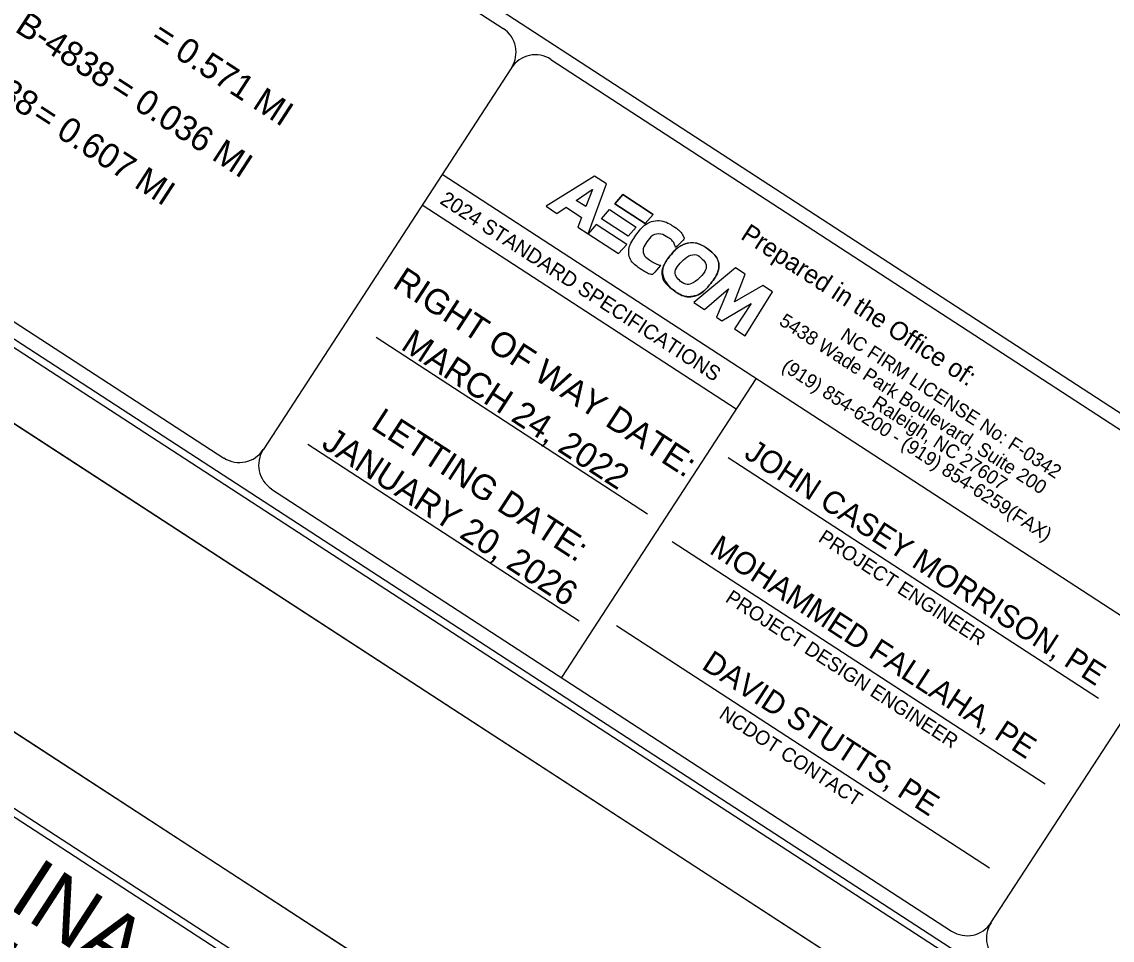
# Model space of a CAD drawing. Extents: x 2291197 to 2302790, y 592892 to 604246.
# Drawn here: x 2296768 to 2298300, y 597905 to 599195 of the extents above; entities that cross this region are included whole.
import ezdxf

# ---------------------------------------------------------------- set-up
doc = ezdxf.new("R2010")
doc.units = 0
for name, color, linetype in [('Default', 7, 'Continuous'), ('Prop DSN Text', 7, 'Continuous'), ('Prop Shade Light', 7, 'Continuous'), ('Sheet Cutting Line CELL', 7, 'Continuous'), ('Sheet Data Field CELL', 7, 'Continuous'), ('Sheet Plot Border Inside CELL', 7, 'Continuous'), ('Sheet Plot Border Outside CELL', 7, 'Continuous'), ('Sheet Symbology CELL', 7, 'Continuous'), ('Sheet Title CELL', 7, 'Continuous')]:
    doc.layers.add(name, color=color, linetype=linetype)

# ---------------------------------------------------------------- blocks, each defined once
blk = doc.blocks.new('block 3')
at = {"layer": 'Default'}
blk.add_open_spline([(0.12275, 0.09393), (0.12554, 0.09373), (0.12726, 0.09146), (0.12695, 0.08843), (0.12663, 0.08531), (0.12411, 0.08298), (0.12127, 0.08318), (0.11848, 0.08338), (0.11676, 0.08565), (0.11707, 0.08868), (0.11739, 0.0918), (0.11991, 0.09413), (0.12275, 0.09393)], degree=3, dxfattribs=at)
blk = doc.blocks.new('PLAN SHEET SYMBOLOGY - New')
at = {"layer": 'Sheet Cutting Line CELL'}
blk.add_line((1439376.56, 921733.15), (1437692.56, 921733.15), dxfattribs=at)
at = {"layer": 'Sheet Plot Border Inside CELL'}
blk.add_lwpolyline([(1437705.56, 920655.6), (1439372.06, 920655.6), (1439372.06, 921710.7), (1437705.56, 921710.7)], close=True, dxfattribs=at)
at = {"layer": 'Sheet Plot Border Outside CELL'}
blk.add_lwpolyline([(1437692.56, 920633.15), (1439376.56, 920633.15), (1439376.56, 921733.15), (1437692.56, 921733.15)], close=True, dxfattribs=at)
at = {"layer": 'Sheet Symbology CELL'}
blk.add_lwpolyline([(1439359.56, 921708.15), (1437859.56, 921708.15), (1437859.56, 920659.17), (1439359.56, 920659.17)], close=True, dxfattribs=at)
for s, height, p in [('STATE OF NORTH CAROLINA, DIVISION OF HIGHWAYS', 21.419, (1438310.12, 921680.19)), ('CONVENTIONAL  PLAN SHEET SYMBOLS', 22.0323, (1438318.25, 921649.31))]:
    blk.add_text(s, height=height, dxfattribs=at).set_placement(p)

msp = doc.modelspace()

# ---------------------------------------------------------------- linework, layer by layer
at = {"layer": 'Prop DSN Text'}
for p, q in [((2297572.8, 598978.2), (2297504.6, 598936)), ((2297563.8, 598897.5), (2297589.3, 598967.5)), ((2297589.3, 598967.5), (2297572.8, 598978.2)), ((2297546.9, 598944.4), (2297569.5, 598959.8)), ((2297569.6, 598959.7), (2297560.4, 598935.7)), ((2297569.5, 598959.8), (2297569.6, 598959.7)), ((2297612.5, 598952.4), (2297601.1, 598939.7)), ((2297655.3, 598924.6), (2297612.5, 598952.4)), ((2297504.6, 598936), (2297519.9, 598926)), ((2297519.9, 598926), (2297532.6, 598934.7)), ((2297532.6, 598934.7), (2297554.5, 598920.4)), ((2297560.4, 598935.7), (2297546.9, 598944.4)), ((2297601.1, 598939.7), (2297643.9, 598911.8)), ((2297554.5, 598920.4), (2297549.3, 598906.9)), ((2297582.5, 598918.6), (2297593.8, 598931.4)), ((2297593.8, 598931.4), (2297631.4, 598906.9)), ((2297643.9, 598911.8), (2297655.3, 598924.6)), ((2297549.3, 598906.9), (2297563.8, 598897.5)), ((2297575.1, 598910.3), (2297563.8, 598897.5)), ((2297617.9, 598882.5), (2297575.1, 598910.3)), ((2297620.1, 598894.1), (2297582.5, 598918.6)), ((2297631.4, 598906.9), (2297620.1, 598894.1)), ((2297563.8, 598897.5), (2297606.6, 598869.7)), ((2297606.6, 598869.7), (2297617.9, 598882.5)), ((2297770.7, 598849.6), (2297712.2, 598801)), ((2297784.4, 598840.6), (2297770.7, 598849.6)), ((2297769.2, 598801.7), (2297784.4, 598840.6)), ((2297727.4, 598791.1), (2297760.8, 598820.1)), ((2297760.8, 598820.1), (2297744.1, 598780.2)), ((2297809.1, 598824.6), (2297769.2, 598801.7)), ((2297784.4, 598754.1), (2297822.8, 598815.7)), ((2297822.8, 598815.7), (2297809.1, 598824.6)), ((2297712.2, 598801), (2297727.4, 598791.1)), ((2297751.8, 598775.2), (2297792.8, 598799.3)), ((2297792.8, 598799.3), (2297769.5, 598763.8)), ((2297744.1, 598780.2), (2297751.8, 598775.2)), ((2297769.5, 598763.8), (2297784.4, 598754.1))]:
    msp.add_line(p, q, dxfattribs=at)
for points in [[(2297549.3, 598906.9), (2297563.8, 598897.5), (2297589.3, 598967.5), (2297572.8, 598978.2), (2297504.6, 598936), (2297519.9, 598926), (2297532.6, 598934.7), (2297554.5, 598920.4), (2297549.3, 598906.9)], [(2297546.9, 598944.4), (2297569.5, 598959.8), (2297569.6, 598959.7), (2297560.4, 598935.7), (2297546.9, 598944.4)], [(2297643.9, 598911.8), (2297601.1, 598939.7), (2297612.5, 598952.4), (2297655.3, 598924.6), (2297643.9, 598911.8)], [(2297620.1, 598894.1), (2297582.5, 598918.6), (2297593.8, 598931.4), (2297631.4, 598906.9), (2297620.1, 598894.1)], [(2297617.9, 598882.5), (2297575.1, 598910.3), (2297563.8, 598897.5), (2297606.6, 598869.7), (2297617.9, 598882.5)], [(2297784.4, 598754.1), (2297822.8, 598815.7), (2297809.1, 598824.6), (2297769.2, 598801.7), (2297784.4, 598840.6), (2297770.7, 598849.6), (2297712.2, 598801), (2297727.4, 598791.1), (2297760.8, 598820.1), (2297744.1, 598780.2), (2297751.8, 598775.2), (2297792.8, 598799.3), (2297769.5, 598763.8), (2297784.4, 598754.1)]]:
    msp.add_lwpolyline(points, dxfattribs=at)
for points in [[(2297666, 598853.2), (2297660.7, 598854), (2297654.4, 598857.7), (2297651.4, 598859.6), (2297641.8, 598865.9), (2297639.7, 598876.6), (2297646.3, 598886.1), (2297653.4, 598896.2), (2297666, 598898.6), (2297676.6, 598891.7), (2297681.6, 598888.4), (2297684.9, 598883.9), (2297686.7, 598878), (2297686.7, 598878), (2297699.1, 598890.7), (2297699.1, 598890.7), (2297695.4, 598898.2), (2297691.2, 598902.9), (2297684.9, 598907), (2297667.4, 598918.4), (2297643.4, 598913.2), (2297630.9, 598895.3), (2297618.7, 598877.9), (2297622.1, 598857.8), (2297639.3, 598846.7), (2297642.3, 598844.7), (2297649, 598840.8), (2297654.3, 598840.1), (2297654.3, 598840.1), (2297666, 598853.2), (2297666, 598853.2)], [(2297666, 598853.2), (2297660.7, 598854), (2297654.4, 598857.7), (2297651.4, 598859.6), (2297641.8, 598865.9), (2297639.7, 598876.6), (2297646.3, 598886.1), (2297653.4, 598896.2), (2297666, 598898.6), (2297676.6, 598891.7), (2297681.6, 598888.4), (2297684.9, 598883.9), (2297686.7, 598878), (2297686.7, 598878), (2297699.1, 598890.7), (2297699.1, 598890.7), (2297695.4, 598898.2), (2297691.2, 598902.9), (2297684.9, 598907), (2297667.4, 598918.4), (2297643.4, 598913.2), (2297630.9, 598895.3), (2297618.7, 598877.9), (2297622.1, 598857.8), (2297639.3, 598846.7), (2297642.3, 598844.7), (2297649, 598840.8), (2297654.3, 598840.1), (2297654.3, 598840.1), (2297666, 598853.2), (2297666, 598853.2)], [(2297677.4, 598824), (2297667.3, 598835.9), (2297667.8, 598852.6), (2297679.3, 598866.8), (2297693.1, 598883.9), (2297716.6, 598887.9), (2297732.5, 598875.9)], [(2297732.5, 598875.9), (2297748, 598864.2), (2297749.5, 598844.4), (2297736.1, 598827.8), (2297722.4, 598810.8), (2297698.8, 598806.8), (2297683, 598818.8), (2297680.8, 598820.4), (2297679, 598822.1), (2297677.4, 598824)], [(2297720.7, 598835.8), (2297729.6, 598844.6), (2297731, 598855.1), (2297724.2, 598861.8), (2297716.8, 598869.1), (2297704.8, 598867.6), (2297695.4, 598858.2), (2297686.4, 598849.4), (2297685.1, 598838.9), (2297691.8, 598832.2), (2297699.2, 598824.9), (2297711.3, 598826.4), (2297720.7, 598835.8)], [(2297720.7, 598835.8), (2297729.6, 598844.6), (2297731, 598855.1), (2297724.2, 598861.8), (2297716.8, 598869.1), (2297704.8, 598867.6), (2297695.4, 598858.2), (2297686.4, 598849.4), (2297685.1, 598838.9), (2297691.8, 598832.2), (2297699.2, 598824.9), (2297711.3, 598826.4), (2297720.7, 598835.8)]]:
    msp.add_open_spline(points, degree=3, dxfattribs=at)
at = {"layer": 'Sheet Cutting Line CELL'}
for p, q in [((2293793.6, 600557.1), (2299441.2, 596885.8)), ((2299242.9, 596580.9), (2293595.3, 600252.2))]:
    msp.add_line(p, q, dxfattribs=at)
at = {"layer": 'Sheet Plot Border Inside CELL'}
msp.add_lwpolyline([(2293886.1, 600604), (2299475, 596970.9), (2301775.2, 600509.4), (2296186.3, 604142.5)], close=True, dxfattribs=at)
at = {"layer": 'Sheet Plot Border Outside CELL'}
msp.add_lwpolyline([(2301839.2, 600574.8), (2296191.6, 604246.1), (2293793.6, 600557.1), (2299441.2, 596885.8)], close=True, dxfattribs=at)
at = {"layer": 'Sheet Title CELL'}
for p, q in [((2295040.3, 600772.4), (2299802.6, 597676.6)), ((2296169.7, 600014.3), (2297444.1, 599185.9)), ((2297511.2, 599142.3), (2298467, 598521)), ((2297455.8, 599130.6), (2297107, 598594)), ((2298381.1, 598315.6), (2297358.3, 598980.5)), ((2297771.6, 598650.9), (2297330.5, 598937.8)), ((2297647.2, 598503.6), (2297265.7, 598751.6)), ((2297644.5, 598733.6), (2297644.5, 598733.6)), ((2297799.4, 598693.7), (2297526.4, 598273.7)), ((2297456.3, 598627.6), (2297456.3, 598627.6)), ((2297551.3, 598353.1), (2297169.8, 598601.1)), ((2297760.5, 598583.2), (2298280.8, 598244.9)), ((2297682, 598465.1), (2298206, 598124.4)), ((2298129.8, 597929), (2298478.7, 598465.6)), ((2297603.6, 598346.9), (2298127.6, 598006.3))]:
    msp.add_line(p, q, dxfattribs=at)
for points in [[(2294441.6, 600255), (2299405.1, 597028.5)], [(2295777.2, 599410.7), (2297051.6, 598582.2)], [(2297118.7, 598538.7), (2298074.5, 597917.3)]]:
    msp.add_lwpolyline(points, dxfattribs=at)
for centre, start, end in [((2297422.4, 599152.5), 326.9737, 56.9737), ((2297489.5, 599108.9), 56.9737, 146.9737), ((2297073.6, 598616), 236.9737, 326.9737), ((2297140.6, 598572.4), 146.9737, 236.9737), ((2298096.4, 597951), 236.9737, 326.9737), ((2298163.5, 597907.4), 146.9737, 236.9737)]:
    msp.add_arc(centre, 40, start, end, dxfattribs=at)

# ---------------------------------------------------------------- block references
at = {"layer": 'Prop DSN Text', "xscale": 6970.9493697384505, "yscale": 6970.949369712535, "rotation": -33.027261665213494}
msp.add_blockref('block 3', (2296658.2, 598793.3), dxfattribs=at)
at = {"layer": 'Prop Shade Light', "xscale": 4, "yscale": 3.9999999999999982, "rotation": -33.02629958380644}
msp.add_blockref('PLAN SHEET SYMBOLOGY - New', (-4537434.8, 643359.8), dxfattribs=at)

# ---------------------------------------------------------------- texts
at = {"layer": 'Prop DSN Text'}
for s, height, p in [('Prepared in the Office of:', 25.818, (2297776.5, 598891.2)), ('5438 Wade Park Boulevard, Suite 200', 19.364, (2297830.7, 598770.5)), ('NC FIRM LICENSE No: F-0342', 19.364, (2297916.7, 598750.1)), ('(919) 854-6200 - (919) 854-6259(FAX)', 19.364, (2297834.3, 598706.8)), ('Raleigh, NC 27607', 19.364, (2297961.2, 598655))]:
    msp.add_text(s, height=height, rotation=326.9727, dxfattribs=at).set_placement(p)
at = {"layer": 'Sheet Data Field CELL'}
for s, height, p in [('MARCH 24, 2022', 35, (2297298.8, 598736.2)), ('JANUARY 20, 2026', 35, (2297187.1, 598597.9)), ('JOHN CASEY MORRISON, PE', 31.5, (2297781.2, 598583.9)), ('MOHAMMED FALLAHA, PE', 31.5, (2297732.4, 598449.3)), ('DAVID STUTTS, PE', 31.5, (2297721.7, 598287.1))]:
    msp.add_text(s, height=height, rotation=326.9737, dxfattribs=at).set_placement(p)
at = {"layer": 'Sheet Title CELL'}
for s, height, p in [('LENGTH STRUCTURE TIP PROJECT B-4838', 35.125, (2296065, 599632.1)), ('TOTAL LENGTH TIP PROJECT B-4838', 35.125, (2296073.7, 599516.6)), ('= 0.571 MI', 35.13, (2296946.8, 599168.7)), ('= 0.036 MI', 35.13, (2296889.6, 599096.1)), ('= 0.607 MI', 35.13, (2296780.5, 599057.2)), ('2024 STANDARD SPECIFICATIONS', 20.8, (2297353.9, 598940.9)), ('RIGHT OF WAY DATE: ', 34.999, (2297287.1, 598823)), ('LETTING DATE:', 34.999, (2297256.9, 598624.9)), ('PROJECT ENGINEER', 19.998, (2297885.8, 598466)), ('PROJECT DESIGN ENGINEER', 19.998, (2297755.2, 598381.4)), ('NCDOT CONTACT', 19.998, (2297746.3, 598218.1))]:
    msp.add_text(s, height=height, rotation=326.9737, dxfattribs=at).set_placement(p)

doc.saveas('drawing.dxf')
